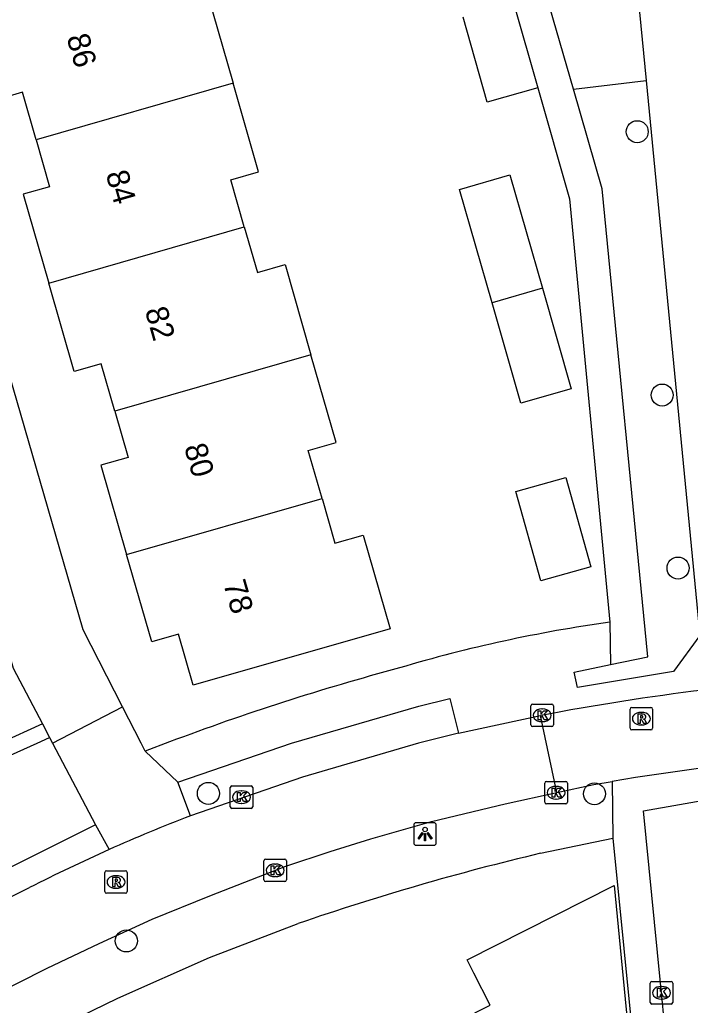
# Model space of a CAD drawing. Extents: x 158461 to 159795, y 387220 to 388672.
# Drawn here: x 159071.64 to 159101.4, y 387988.35 to 388032.14 of the extents above; entities that cross this region are included whole.
import ezdxf

# ---------------------------------------------------------------- set-up
doc = ezdxf.new("R2010")
doc.units = 0
for name, color, linetype in [('IMGEO_Boom', 7, 'Continuous'), ('IMGEO_Fietspad_gesloten', 7, 'Continuous'), ('IMGEO_Groenvoorziening', 7, 'Continuous'), ('IMGEO_Kolk', 7, 'Continuous'), ('IMGEO_Lichtpunt', 7, 'Continuous'), ('IMGEO_Pand', 7, 'Continuous'), ('IMGEO_Pand_nummerreeks', 7, 'Continuous'), ('IMGEO_Rijbaan_lokaal_open', 7, 'Continuous'), ('IMGEO_Rioolput', 7, 'Continuous'), ('IMGEO_Voetpad_open', 7, 'Continuous')]:
    doc.layers.add(name, color=color, linetype=linetype)

msp = doc.modelspace()

# ---------------------------------------------------------------- linework, layer by layer
at = {"layer": 'IMGEO_Boom'}
for centre in [(159099.047, 388027.161), (159100.155, 388015.462), (159100.86, 388007.777), (159080.013, 387997.764), (159097.151, 387997.748), (159076.368, 387991.213)]:
    msp.add_circle(centre, 0.489, dxfattribs=at)
at = {"layer": 'IMGEO_Fietspad_gesloten'}
for points in [[(159098.11, 388043.12), (159099.438, 388029.434)], [(159099.438, 388029.434), (159101.83, 388004.777)]]:
    msp.add_lwpolyline(points, dxfattribs=at)
at = {"layer": 'IMGEO_Groenvoorziening'}
msp.add_lwpolyline([(159096.218, 388029.047), (159099.438, 388029.434)], dxfattribs=at)
at = {"layer": 'IMGEO_Kolk'}
for p, q in [((159094.329, 388000.81), (159094.329, 388001.662)), ((159094.404, 388001.736), (159095.256, 388001.736)), ((159095.33, 388001.662), (159095.33, 388000.81)), ((159094.817, 388001.516), (159094.842, 388001.516)), ((159095.256, 388000.736), (159094.404, 388000.736)), ((159094.84, 388000.956), (159094.815, 388000.956)), ((159081.057, 387998.102), (159081.909, 387998.102)), ((159094.945, 387997.371), (159094.945, 387998.223)), ((159095.02, 387998.297), (159095.872, 387998.297)), ((159095.433, 387998.077), (159095.458, 387998.077)), ((159095.946, 387998.223), (159095.946, 387997.371)), ((159080.982, 387997.176), (159080.982, 387998.028)), ((159081.47, 387997.882), (159081.495, 387997.882)), ((159081.983, 387998.028), (159081.983, 387997.176)), ((159081.493, 387997.322), (159081.468, 387997.322)), ((159095.872, 387997.297), (159095.02, 387997.297)), ((159095.456, 387997.517), (159095.431, 387997.517)), ((159081.909, 387997.102), (159081.057, 387997.102)), ((159082.476, 387993.923), (159082.476, 387994.775)), ((159082.551, 387994.849), (159083.403, 387994.849)), ((159082.964, 387994.629), (159082.989, 387994.629)), ((159083.477, 387994.775), (159083.477, 387993.923)), ((159083.403, 387993.849), (159082.551, 387993.849)), ((159082.987, 387994.069), (159082.962, 387994.069)), ((159099.626, 387988.484), (159099.626, 387989.336)), ((159099.701, 387989.41), (159100.553, 387989.41)), ((159100.627, 387989.336), (159100.627, 387988.484)), ((159100.114, 387989.19), (159100.139, 387989.19)), ((159100.137, 387988.63), (159100.112, 387988.63)), ((159100.553, 387988.41), (159099.701, 387988.41))]:
    msp.add_line(p, q, dxfattribs=at)
for points in [[(159094.329, 388000.81), (159094.329, 388001.662)], [(159094.404, 388001.736), (159095.256, 388001.736)], [(159095.33, 388001.662), (159095.33, 388000.81)], [(159094.65, 388001.436), (159094.773, 388001.436), (159094.773, 388001.285), (159094.903, 388001.436), (159095.067, 388001.436), (159094.921, 388001.285), (159095.074, 388001.036), (159094.922, 388001.036), (159094.837, 388001.2), (159094.773, 388001.133), (159094.773, 388001.036), (159094.65, 388001.036), (159094.65, 388001.436)], [(159095.256, 388000.736), (159094.404, 388000.736)], [(159081.057, 387998.102), (159081.909, 387998.102)], [(159094.945, 387997.371), (159094.945, 387998.223)], [(159095.02, 387998.297), (159095.872, 387998.297)], [(159095.946, 387998.223), (159095.946, 387997.371)], [(159080.982, 387997.176), (159080.982, 387998.028)], [(159081.303, 387997.802), (159081.426, 387997.802), (159081.426, 387997.651), (159081.556, 387997.802), (159081.72, 387997.802), (159081.574, 387997.651), (159081.727, 387997.402), (159081.575, 387997.402), (159081.49, 387997.566), (159081.426, 387997.499), (159081.426, 387997.402), (159081.303, 387997.402), (159081.303, 387997.802)], [(159081.983, 387998.028), (159081.983, 387997.176)], [(159095.266, 387997.997), (159095.389, 387997.997), (159095.389, 387997.846), (159095.519, 387997.997), (159095.683, 387997.997), (159095.537, 387997.846), (159095.69, 387997.597), (159095.538, 387997.597), (159095.453, 387997.761), (159095.389, 387997.694), (159095.389, 387997.597), (159095.266, 387997.597), (159095.266, 387997.997)], [(159095.872, 387997.297), (159095.02, 387997.297)], [(159081.909, 387997.102), (159081.057, 387997.102)], [(159082.476, 387993.923), (159082.476, 387994.775)], [(159082.551, 387994.849), (159083.403, 387994.849)], [(159083.477, 387994.775), (159083.477, 387993.923)], [(159082.797, 387994.549), (159082.92, 387994.549), (159082.92, 387994.398), (159083.05, 387994.549), (159083.214, 387994.549), (159083.068, 387994.398), (159083.221, 387994.149), (159083.069, 387994.149), (159082.984, 387994.313), (159082.92, 387994.246), (159082.92, 387994.149), (159082.797, 387994.149), (159082.797, 387994.549)], [(159083.403, 387993.849), (159082.551, 387993.849)], [(159099.626, 387988.484), (159099.626, 387989.336)], [(159099.701, 387989.41), (159100.553, 387989.41)], [(159100.627, 387989.336), (159100.627, 387988.484)], [(159099.947, 387989.11), (159100.07, 387989.11), (159100.07, 387988.959), (159100.2, 387989.11), (159100.364, 387989.11), (159100.218, 387988.959), (159100.371, 387988.71), (159100.219, 387988.71), (159100.134, 387988.874), (159100.07, 387988.807), (159100.07, 387988.71), (159099.947, 387988.71), (159099.947, 387989.11)], [(159100.553, 387988.41), (159099.701, 387988.41)]]:
    msp.add_lwpolyline(points, dxfattribs=at)
for centre, start, end in [((159094.406, 388001.66), 91.552, 178.448), ((159094.406, 388001.66), 91.552, 178.448), ((159095.254, 388001.66), 1.552, 88.448), ((159095.254, 388001.66), 1.552, 88.448), ((159094.406, 388000.812), 181.552, 268.448), ((159094.406, 388000.812), 181.552, 268.448), ((159095.254, 388000.812), 271.552, 358.448), ((159095.254, 388000.812), 271.552, 358.448), ((159081.059, 387998.026), 91.552, 178.448), ((159081.059, 387998.026), 91.552, 178.448), ((159081.907, 387998.026), 1.552, 88.448), ((159081.907, 387998.026), 1.552, 88.448), ((159095.022, 387998.221), 91.552, 178.448), ((159095.022, 387998.221), 91.552, 178.448), ((159095.87, 387998.221), 1.552, 88.448), ((159095.87, 387998.221), 1.552, 88.448), ((159095.022, 387997.373), 181.552, 268.448), ((159095.022, 387997.373), 181.552, 268.448), ((159095.87, 387997.373), 271.552, 358.448), ((159095.87, 387997.373), 271.552, 358.448), ((159081.059, 387997.178), 181.552, 268.448), ((159081.059, 387997.178), 181.552, 268.448), ((159081.907, 387997.178), 271.552, 358.448), ((159081.907, 387997.178), 271.552, 358.448), ((159082.553, 387994.773), 91.552, 178.448), ((159082.553, 387994.773), 91.552, 178.448), ((159083.401, 387994.773), 1.552, 88.448), ((159083.401, 387994.773), 1.552, 88.448), ((159082.553, 387993.925), 181.552, 268.448), ((159082.553, 387993.925), 181.552, 268.448), ((159083.401, 387993.925), 271.552, 358.448), ((159083.401, 387993.925), 271.552, 358.448), ((159099.703, 387989.334), 91.552, 178.448), ((159099.703, 387989.334), 91.552, 178.448), ((159100.551, 387989.334), 1.552, 88.448), ((159100.551, 387989.334), 1.552, 88.448), ((159099.703, 387988.486), 181.552, 268.448), ((159099.703, 387988.486), 181.552, 268.448), ((159100.551, 387988.486), 271.552, 358.448), ((159100.551, 387988.486), 271.552, 358.448)]:
    msp.add_arc(centre, 0.0765, start, end, dxfattribs=at)
for centre, major_axis, ratio, start_param, end_param in [((159094.816, 388001.236), (-0.387, 0.002), 0.722429, 4.712389, 7.853982), ((159094.841, 388001.236), (-0.39, 0.002), 0.717154, 1.570796, 4.712389), ((159095.432, 387997.797), (-0.387, 0.002), 0.722429, 4.712389, 7.853982), ((159095.457, 387997.797), (-0.39, 0.002), 0.717154, 1.570796, 4.712389), ((159081.469, 387997.602), (-0.387, 0.002), 0.722429, 4.712389, 7.853982), ((159081.494, 387997.602), (-0.39, 0.002), 0.717154, 1.570796, 4.712389), ((159082.963, 387994.349), (-0.387, 0.002), 0.722429, 4.712389, 7.853982), ((159082.988, 387994.349), (-0.39, 0.002), 0.717154, 1.570796, 4.712389), ((159100.113, 387988.91), (-0.387, 0.002), 0.722429, 4.712389, 7.853982), ((159100.138, 387988.91), (-0.39, 0.002), 0.717154, 1.570796, 4.712389)]:
    msp.add_ellipse(centre, major_axis=major_axis, ratio=ratio, start_param=start_param, end_param=end_param, dxfattribs=at)
at = {"layer": 'IMGEO_Lichtpunt'}
for p, q in [((159089.131, 387996.365), (159089.131, 387995.558)), ((159089.131, 387996.365), (159089.131, 387995.558)), ((159090.033, 387996.46), (159089.225, 387996.46)), ((159090.033, 387996.46), (159089.225, 387996.46)), ((159090.127, 387995.558), (159090.127, 387996.365)), ((159090.127, 387995.558), (159090.127, 387996.365)), ((159089.225, 387995.464), (159090.033, 387995.464)), ((159089.225, 387995.464), (159090.033, 387995.464))]:
    msp.add_line(p, q, dxfattribs=at)
for points in [[(159089.505, 387996.029), (159089.544, 387996.001), (159089.356, 387995.739), (159089.318, 387995.766), (159089.505, 387996.029)], [(159089.607, 387995.981), (159089.654, 387995.981), (159089.654, 387995.659), (159089.607, 387995.659), (159089.607, 387995.981)], [(159089.717, 387996.001), (159089.755, 387996.028), (159089.942, 387995.766), (159089.903, 387995.738), (159089.717, 387996.001)]]:
    msp.add_lwpolyline(points, dxfattribs=at)
msp.add_circle((159089.63, 387996.163), 0.0994, dxfattribs=at)
for centre, start, end in [((159089.225, 387996.365), 90, 180), ((159089.225, 387996.365), 90, 180), ((159090.033, 387996.365), 0, 90), ((159090.033, 387996.365), 0, 90), ((159089.225, 387995.558), 180, 270), ((159089.225, 387995.558), 180, 270), ((159090.033, 387995.558), 270, 0), ((159090.033, 387995.558), 270, 360)]:
    msp.add_arc(centre, 0.0946, start, end, dxfattribs=at)
at = {"layer": 'IMGEO_Pand'}
for points in [[(159072.363, 388026.799), (159071.757, 388028.911), (159070.559, 388028.567), (159069.402, 388032.599), (159078.086, 388035.091), (159078.707, 388032.927), (159079.97, 388033.29), (159081.111, 388029.313)], [(159093.559, 388032.89), (159094.637, 388029.107)], [(159094.637, 388029.107), (159092.392, 388028.468), (159091.316, 388032.246)], [(159081.111, 388029.313), (159072.363, 388026.799)], [(159081.606, 388022.929), (159081.006, 388025.022), (159082.241, 388025.376), (159081.349, 388028.484), (159081.111, 388029.313)], [(159072.363, 388026.799), (159072.96, 388024.719), (159071.796, 388024.385), (159072.929, 388020.437)], [(159092.602, 388019.563), (159091.159, 388024.598), (159093.397, 388025.239), (159094.84, 388020.205)], [(159072.929, 388020.437), (159081.606, 388022.929)], [(159081.606, 388022.929), (159082.188, 388020.902), (159083.418, 388021.255), (159084.566, 388017.254)], [(159075.856, 388014.752), (159075.255, 388016.845), (159074.058, 388016.502), (159072.929, 388020.437)], [(159094.84, 388020.205), (159096.119, 388015.743), (159093.881, 388015.102), (159092.602, 388019.563)], [(159094.84, 388020.205), (159092.602, 388019.563)], [(159084.566, 388017.254), (159075.856, 388014.752)], [(159085.056, 388010.869), (159084.445, 388013), (159085.685, 388013.355), (159084.566, 388017.254)], [(159075.856, 388014.752), (159076.448, 388012.69), (159075.244, 388012.344), (159076.382, 388008.378)], [(159094.766, 388007.204), (159093.655, 388011.181), (159095.885, 388011.804), (159096.996, 388007.827), (159094.766, 388007.204)], [(159076.382, 388008.378), (159085.056, 388010.869)], [(159085.056, 388010.869), (159085.627, 388008.879), (159086.887, 388009.241), (159088.08, 388005.083), (159079.336, 388002.574), (159078.684, 388004.846), (159077.494, 388004.504), (159076.382, 388008.378)], [(159087.156, 387985.651), (159092.518, 387988.363), (159091.801, 387989.781), (159091.499, 387990.38), (159098.024, 387993.677), (159099.058, 387982.972), (159096.38, 387981.618), (159090.66, 387978.725)]]:
    msp.add_lwpolyline(points, dxfattribs=at)
at = {"layer": 'IMGEO_Rijbaan_lokaal_open'}
for points in [[(159091.113, 388000.442), (159094.753, 388001.222)], [(159095.486, 387997.804), (159094.753, 388001.222)], [(159091.113, 388000.442), (159089.339, 388000), (159084.196, 387998.488), (159079.213, 387996.771)], [(159102.4, 387998.948), (159101.874, 387998.89), (159098.978, 387998.476), (159097.931, 387998.297)], [(159095.486, 387997.804), (159097.119, 387998.159), (159097.931, 387998.297)], [(159064.908, 387985.996), (159072.86, 387990.004), (159075.16, 387991.099), (159077.52, 387992.185), (159080.081, 387993.219), (159083.451, 387994.533), (159085.411, 387995.19), (159087.221, 387995.746), (159089.91, 387996.522), (159093.189, 387997.305), (159095.486, 387997.804)], [(159063.134, 387989.009), (159068.795, 387991.948), (159072.076, 387993.581)]]:
    msp.add_lwpolyline(points, dxfattribs=at)
for centre, radius, start, end in [((159115.118, 387895.023), 108.134, 96.96543, 100.85565), ((159105.81, 387927.646), 74.066, 111.04528, 114.07046), ((159106.232, 387926.841), 74.972, 114.11398, 117.10251)]:
    msp.add_arc(centre, radius, start, end, dxfattribs=at)
at = {"layer": 'IMGEO_Rioolput'}
for p, q in [((159098.806, 388001.587), (159099.658, 388001.587)), ((159098.731, 388000.661), (159098.731, 388001.513)), ((159099.219, 388001.367), (159099.244, 388001.367)), ((159099.732, 388001.513), (159099.732, 388000.661)), ((159099.242, 388000.807), (159099.217, 388000.807)), ((159099.658, 388000.587), (159098.806, 388000.587)), ((159075.411, 387993.405), (159075.411, 387994.257)), ((159075.486, 387994.331), (159076.338, 387994.331)), ((159076.412, 387994.257), (159076.412, 387993.405)), ((159075.899, 387994.111), (159075.924, 387994.111)), ((159076.338, 387993.331), (159075.486, 387993.331)), ((159075.922, 387993.551), (159075.897, 387993.551))]:
    msp.add_line(p, q, dxfattribs=at)
for points in [[(159098.806, 388001.587), (159099.658, 388001.587)], [(159098.731, 388000.661), (159098.731, 388001.513)], [(159099.32, 388001.285), (159099.068, 388001.287), (159099.068, 388000.887)], [(159099.246, 388001.206), (159099.192, 388001.206), (159099.192, 388001.125)], [(159099.192, 388001.125), (159099.244, 388001.125)], [(159099.732, 388001.513), (159099.732, 388000.661)], [(159099.068, 388000.887), (159099.192, 388000.887), (159099.192, 388001.049), (159099.203, 388001.049)], [(159099.25, 388001.02), (159099.321, 388000.887), (159099.461, 388000.887), (159099.396, 388001.013)], [(159099.658, 388000.587), (159098.806, 388000.587)], [(159075.411, 387993.405), (159075.411, 387994.257)], [(159075.486, 387994.331), (159076.338, 387994.331)], [(159076.412, 387994.257), (159076.412, 387993.405)], [(159076, 387994.029), (159075.748, 387994.031), (159075.748, 387993.631)], [(159075.748, 387993.631), (159075.872, 387993.631), (159075.872, 387993.793), (159075.883, 387993.793)], [(159075.926, 387993.95), (159075.872, 387993.95), (159075.872, 387993.869)], [(159075.872, 387993.869), (159075.924, 387993.869)], [(159075.93, 387993.764), (159076.001, 387993.631), (159076.141, 387993.631), (159076.076, 387993.757)], [(159076.338, 387993.331), (159075.486, 387993.331)]]:
    msp.add_lwpolyline(points, dxfattribs=at)
for centre, radius, start, end in [((159098.808, 388001.511), 0.0765, 91.552, 178.448), ((159098.808, 388001.511), 0.0765, 91.552, 178.448), ((159099.656, 388001.511), 0.0765, 1.552, 88.448), ((159099.656, 388001.511), 0.0765, 1.552, 88.448), ((159099.228, 388001.314), 0.19, 274.7715, 282.9687), ((159099.252, 388001.11), 0.0964, 77.0061, 93.1865), ((159099.266, 388001.167), 0.0378, 276.6634, 79.6772), ((159099.319, 388001.175), 0.109, 350.3612, 89.416), ((159099.317, 388001.175), 0.112, 277.5842, 350.9817), ((159099.202, 388000.996), 0.0533, 26.0293, 88.6989), ((159099.301, 388000.96), 0.108, 29.5134, 73.7905), ((159098.808, 388000.663), 0.0765, 181.552, 268.448), ((159098.808, 388000.663), 0.0765, 181.552, 268.448), ((159099.656, 388000.663), 0.0765, 271.552, 358.448), ((159099.656, 388000.663), 0.0765, 271.552, 358.448), ((159075.488, 387994.255), 0.0765, 91.552, 178.448), ((159075.488, 387994.255), 0.0765, 91.552, 178.448), ((159076.336, 387994.255), 0.0765, 1.552, 88.448), ((159076.336, 387994.255), 0.0765, 1.552, 88.448), ((159075.882, 387993.74), 0.0533, 26.0293, 88.6989), ((159075.908, 387994.058), 0.19, 274.7715, 282.9687), ((159075.932, 387993.854), 0.0964, 77.0061, 93.1865), ((159075.946, 387993.911), 0.0378, 276.6634, 79.6772), ((159075.999, 387993.919), 0.109, 350.3612, 89.416), ((159075.997, 387993.919), 0.112, 277.5842, 350.9817), ((159075.981, 387993.704), 0.108, 29.5134, 73.7905), ((159075.488, 387993.407), 0.0765, 181.552, 268.448), ((159075.488, 387993.407), 0.0765, 181.552, 268.448), ((159076.336, 387993.407), 0.0765, 271.552, 358.448), ((159076.336, 387993.407), 0.0765, 271.552, 358.448)]:
    msp.add_arc(centre, radius, start, end, dxfattribs=at)
for centre, major_axis, ratio, start_param, end_param in [((159099.218, 388001.087), (-0.387, 0.002), 0.722429, 4.712389, 7.853982), ((159099.243, 388001.087), (-0.39, 0.002), 0.717154, 1.570796, 4.712389), ((159075.898, 387993.831), (-0.387, 0.002), 0.722429, 4.712389, 7.853982), ((159075.923, 387993.831), (-0.39, 0.002), 0.717154, 1.570796, 4.712389)]:
    msp.add_ellipse(centre, major_axis=major_axis, ratio=ratio, start_param=start_param, end_param=end_param, dxfattribs=at)
at = {"layer": 'IMGEO_Voetpad_open'}
for points in [[(159096.218, 388029.047), (159092.611, 388041.539)], [(159076.201, 388001.612), (159074.45, 388005.028), (159066.145, 388033.716)], [(159094.637, 388029.107), (159096.036, 388024.178), (159097.829, 388005.371)], [(159097.856, 388003.486), (159099.516, 388003.83), (159097.495, 388024.625), (159096.218, 388029.047)], [(159072.646, 388000.854), (159070.749, 388000), (159060.035, 387995.179), (159057.79, 388000), (159053.478, 388009.256), (159048.748, 388007.145)], [(159097.829, 388005.371), (159097.856, 388003.486)], [(159101.83, 388004.777), (159100.664, 388003.179), (159096.396, 388002.466), (159096.256, 388003.155), (159097.856, 388003.486)], [(159071.15, 388004.018), (159071.35, 388003.324), (159072.646, 388000.854)], [(159073.095, 388000), (159076.201, 388001.612)], [(159077.211, 387999.639), (159077.027, 388000), (159076.201, 388001.612)], [(159078.65, 387998.258), (159083.703, 388000), (159089.348, 388001.645), (159090.734, 388001.986), (159091.113, 388000.442)], [(159072.646, 388000.854), (159072.962, 388000.252)], [(159074.999, 387996.372), (159062.413, 387990.073), (159060.322, 387994.563), (159072.403, 388000), (159072.962, 388000.252)], [(159072.962, 388000.252), (159073.095, 388000)], [(159073.095, 388000), (159074.999, 387996.372)], [(159078.285, 388000.052), (159077.211, 387999.639)], [(159077.211, 387999.639), (159078.65, 387998.258)], [(159079.213, 387996.771), (159078.65, 387998.258)], [(159097.931, 387998.297), (159097.967, 387995.774)], [(159102.367, 387966.418), (159101.06, 387979.46), (159099.326, 387996.997), (159102.524, 387997.555)], [(159074.999, 387996.372), (159075.602, 387995.271)], [(159094.755, 387995.105), (159097.967, 387995.774)], [(159097.967, 387995.774), (159100.372, 387971.562)], [(159066.645, 387984.129), (159075.992, 387988.664), (159080.06, 387990.475), (159083.997, 387991.984)]]:
    msp.add_lwpolyline(points, dxfattribs=at)
for centre, radius, start, end in [((159106.592, 387942.657), 63.324, 97.95473, 106.60997), ((159116.368, 387899.262), 107.744, 104.99486, 110.69888), ((159121.06, 387884.33), 113.855, 103.35832, 108.9976)]:
    msp.add_arc(centre, radius, start, end, dxfattribs=at)

# ---------------------------------------------------------------- texts
at = {"layer": 'IMGEO_Pand_nummerreeks'}
for s, p in [('86', (159073.707, 388031.357)), ('84', (159075.445, 388025.291)), ('82', (159077.183, 388019.229)), ('80', (159078.924, 388013.158)), ('78', (159080.662, 388007.093))]:
    msp.add_text(s, height=1, rotation=285.996, dxfattribs=at).set_placement(p)

doc.saveas('drawing.dxf')
